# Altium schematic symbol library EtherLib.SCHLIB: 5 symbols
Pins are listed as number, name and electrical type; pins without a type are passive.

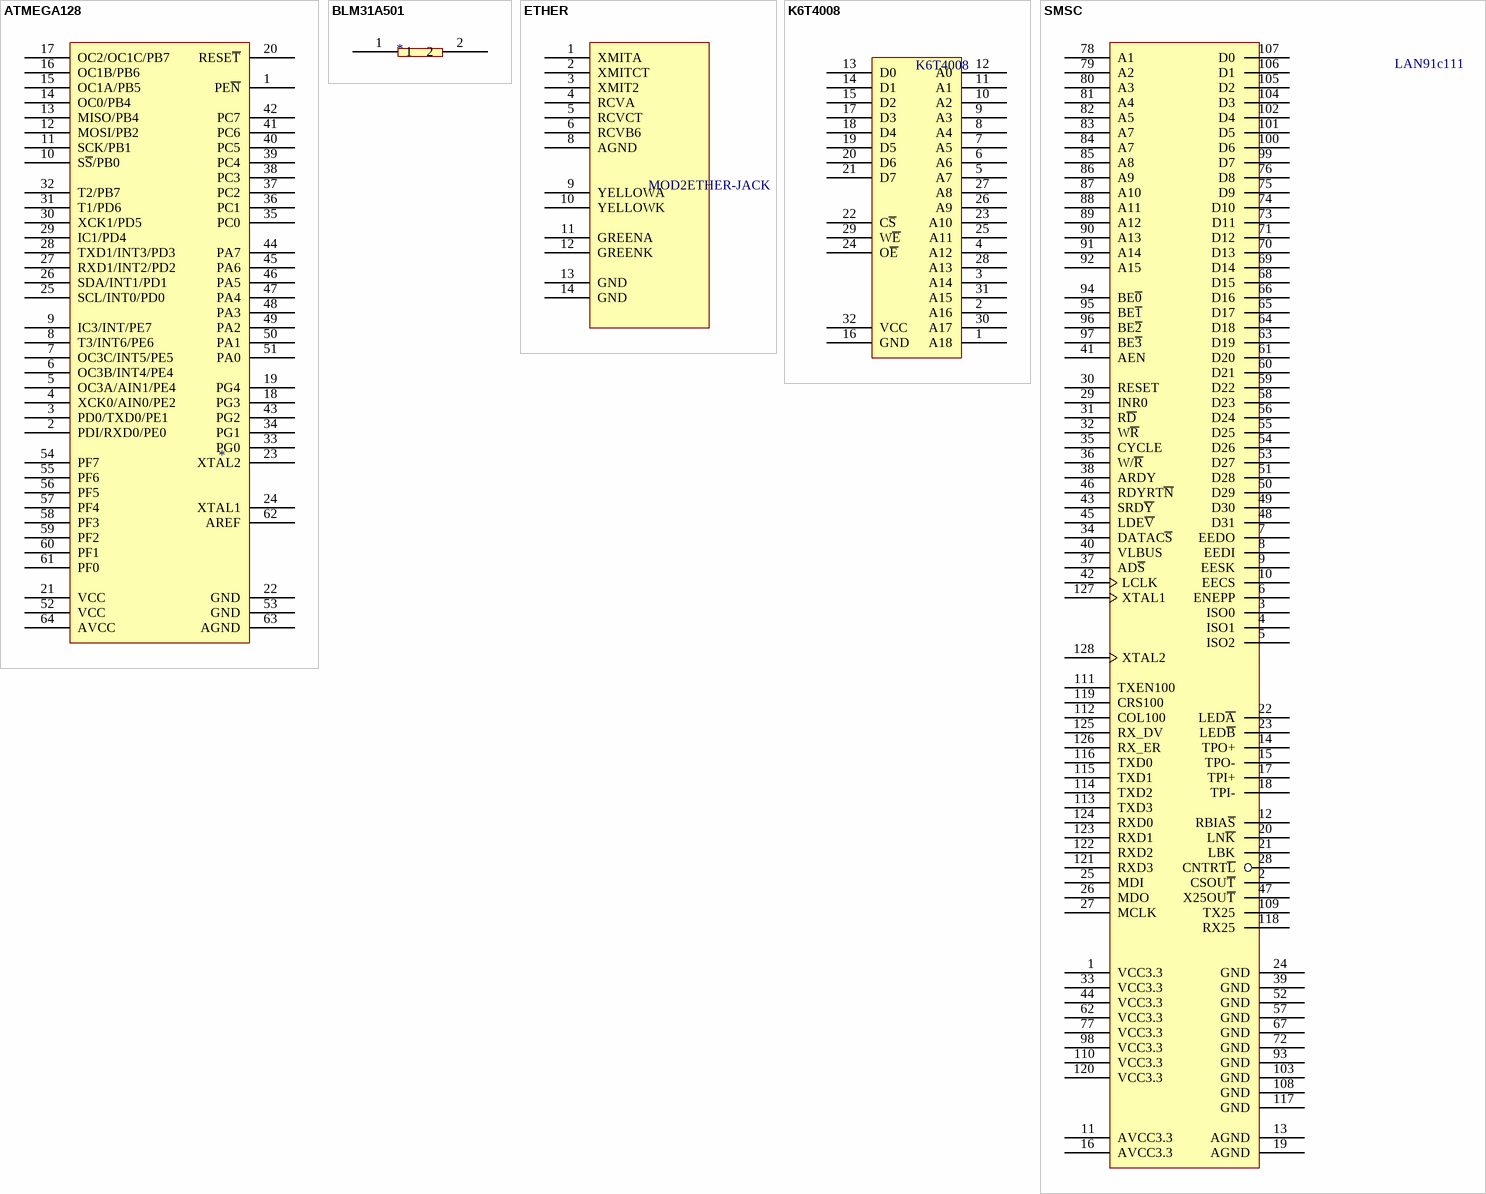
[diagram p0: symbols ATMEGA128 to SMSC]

## ATMEGA128
designator *
pins: 1 PE~{N}, 2 PDI/RXD0/PE0, 3 PD0/TXD0/PE1, 4 XCK0/AIN0/PE2, 5 OC3A/AIN1/PE4, 6 OC3B/INT4/PE4, 7 OC3C/INT5/PE5, 8 T3/INT6/PE6, 9 IC3/INT/PE7, 10 S~{S}/PB0, 11 SCK/PB1, 12 MOSI/PB2, 13 MISO/PB4, 14 OC0/PB4, 15 OC1A/PB5, 16 OC1B/PB6, 17 OC2/OC1C/PB7, 18 PG3, 19 PG4, 20 RESE~{T}, 21 VCC, 22 GND, 23 XTAL2, 24 XTAL1, 25 SCL/INT0/PD0, 26 SDA/INT1/PD1, 27 RXD1/INT2/PD2, 28 TXD1/INT3/PD3, 29 IC1/PD4, 30 XCK1/PD5, 31 T1/PD6, 32 T2/PB7, 33 PG0, 34 PG1, 35 PC0, 36 PC1, 37 PC2, 38 PC3, 39 PC4, 40 PC5, 41 PC6, 42 PC7, 43 PG2, 44 PA7, 45 PA6, 46 PA5, 47 PA4, 48 PA3, 49 PA2, 50 PA1, 51 PA0, 52 VCC, 53 GND, 54 PF7, 55 PF6, 56 PF5, 57 PF4, 58 PF3, 59 PF2, 60 PF1, 61 PF0, 62 AREF, 63 AGND, 64 AVCC

## BLM31A501
designator *
pins: 1, 2

## ETHER
designator MOD2ETHER-JACK
pins: 1 XMITA, 2 XMITCT, 3 XMIT2, 4 RCVA, 5 RCVCT, 6 RCVB6, 8 AGND, 9 YELLOWA, 10 YELLOWK, 11 GREENA, 12 GREENK, 13 GND, 14 GND

## K6T4008
designator K6T4008
pins: 1 A18, 2 A16, 3 A14, 4 A12, 5 A7, 6 A6, 7 A5, 8 A4, 9 A3, 10 A2, 11 A1, 12 A0, 13 D0, 14 D1, 15 D2, 16 GND, 17 D3, 18 D4, 19 D5, 20 D6, 21 D7, 22 C~{S}, 23 A10, 24 O~{E}, 25 A11, 26 A9, 27 A8, 28 A13, 29 W~{E}, 30 A17, 31 A15, 32 VCC

## SMSC
designator LAN91c111
footprint Model Name (Model Description); pin to pad 2>132 3>27 4>21 5>44 6>17 7>51 8>50 9>49 10>48 11>76 12>15 13>130 14>26 15>23 16>110 17>25 18>14 19>131 20>93 21>100 23>39 24>120 25>12 26>13 27>99 28>16 39>11 44>5 48>10 49>53 50>54 51>55 53>56 54>9 55>58 56>59 58>60 59>61 60>62 61>63 63>64 64>65 65>66 66>8 76>2 93>3 99>101 100>102 101>20 102>104 104>105 105>106 106>107 107>24 112>78 113>7 114>6 116>4 117>129 118>98 119>77
pins: 1 VCC3.3, 2 CSOU~{T}, 3 ISO0, 4 ISO1, 5 ISO2, 6 ENEPP, 7 EEDO, 8 EEDI, 9 EESK, 10 EECS, 11 AVCC3.3, 12 RBIA~{S}, 13 AGND, 14 TPO+, 15 TPO-, 16 AVCC3.3, 17 TPI+, 18 TPI-, 19 AGND, 20 LN~{K}, 21 LBK, 22 LED~{A}, 23 LED~{B}, 24 GND, 25 MDI, 26 MDO, 27 MCLK, 28 CNTRT~{L}, 29 INR0, 30 RESET, 31 R~{D}, 32 W~{R}, 33 VCC3.3, 34 DATAC~{S}, 35 CYCLE, 36 W/~{R}, 37 AD~{S}, 38 ARDY, 39 GND, 40 VLBUS, 41 AEN, 42 LCLK, 43 SRD~{Y}, 44 VCC3.3, 45 LDE~{V}, 46 RDYRT~{N}, 47 X25OU~{T}, 48 D31, 49 D30, 50 D29, 51 D28, 52 GND, 53 D27, 54 D26, 55 D25, 56 D24, 57 GND, 58 D23, 59 D22, 60 D21, 61 D20, 62 VCC3.3, 63 D19, 64 D18, 65 D17, 66 D16, 67 GND, 68 D15, 69 D14, 70 D13, 71 D12, 72 GND, 73 D11, 74 D10, 75 D9, 76 D8, 77 VCC3.3, 78 A1, 79 A2, 80 A3, 81 A4, 82 A5, 83 A7, 84 A7, 85 A8, 86 A9, 87 A10, 88 A11, 89 A12, 90 A13, 91 A14, 92 A15, 93 GND, 94 BE~{0}, 95 BE~{1}, 96 BE~{2}, 97 BE~{3}, 98 VCC3.3, 99 D7, 100 D6, 101 D5, 102 D4, 103 GND, 104 D3, 105 D2, 106 D1, 107 D0, 108 GND, 109 TX25, 110 VCC3.3, 111 TXEN100, 112 COL100, 113 TXD3, 114 TXD2, 115 TXD1, 116 TXD0, 117 GND, 118 RX25, 119 CRS100, 120 VCC3.3, 121 RXD3, 122 RXD2, 123 RXD1, 124 RXD0, 125 RX_DV, 126 RX_ER, 127 XTAL1, 128 XTAL2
